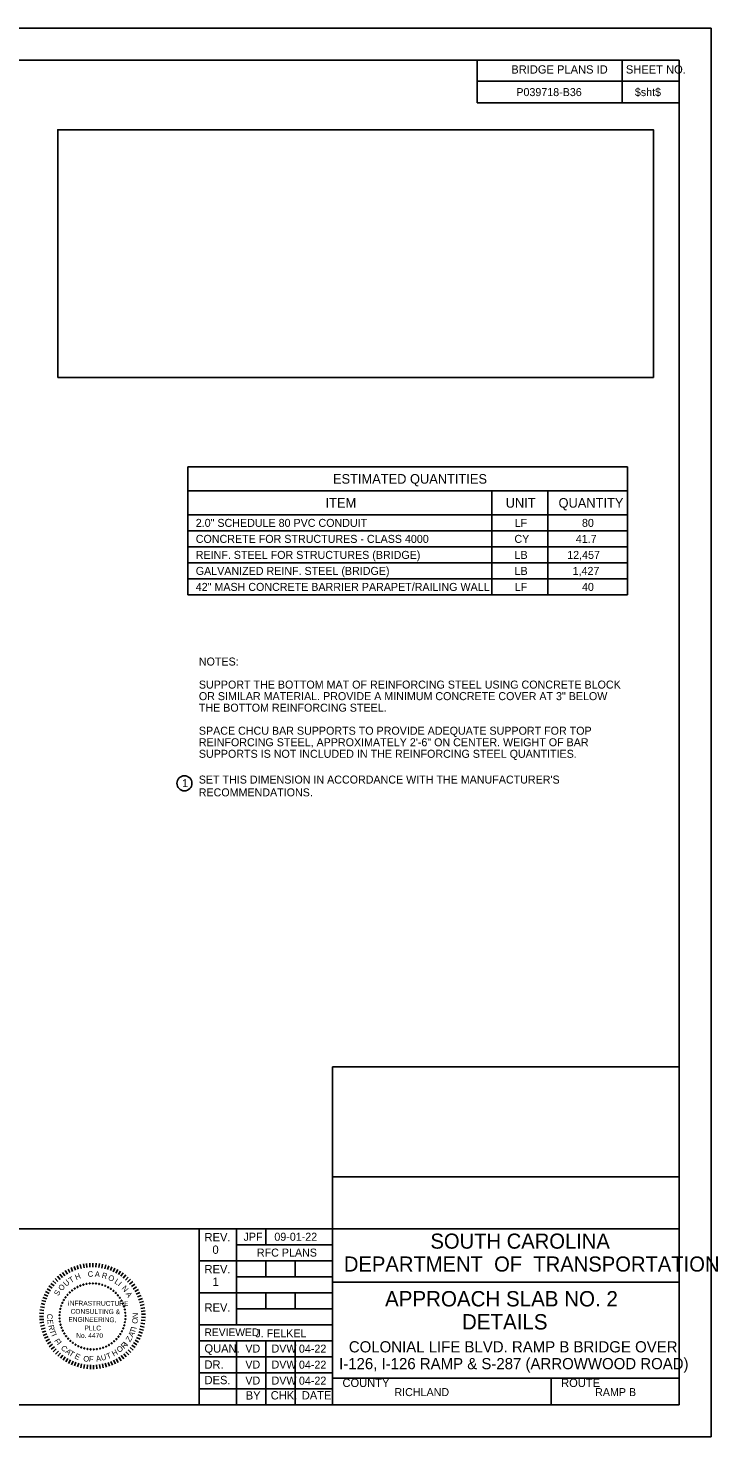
# Model space of a CAD drawing. Extents: x 2799.7 to 2896, y 515.2 to 573.9.
# Drawn here: x 2867.2 to 2896, y 515.2 to 573.9 of the extents above; entities that cross this region are included whole.
import ezdxf

# ---------------------------------------------------------------- set-up
doc = ezdxf.new("R2010")
doc.units = 0
for name, color, linetype in [('BR_AUTO DIMENSION', 7, 'Continuous'), ('BR_BORDER LINES', 7, 'Continuous'), ('BR_TABLE LINES', 7, 'Continuous'), ('BR_TEXT', 7, 'Continuous'), ('Level 31', 7, 'Continuous')]:
    doc.layers.add(name, color=color, linetype=linetype)

msp = doc.modelspace()

# ---------------------------------------------------------------- linework, layer by layer
at = {"layer": 'BR_AUTO DIMENSION'}
msp.add_lwpolyline([(2868.463, 559.346), (2893.292, 559.346), (2893.292, 569.657), (2868.463, 569.657)], close=True, dxfattribs=at)
msp.add_circle((2873.747, 542.44), 0.314, dxfattribs=at)
at = {"layer": 'BR_BORDER LINES'}
for p, q in [((2894.359, 572.556), (2804.582, 572.556)), ((2885.953, 570.779), (2885.953, 572.556)), ((2891.996, 570.779), (2891.996, 572.556)), ((2894.359, 516.556), (2894.359, 572.556)), ((2885.953, 571.678), (2894.359, 571.678)), ((2891.996, 571.678), (2894.359, 571.678)), ((2894.359, 570.779), (2885.953, 570.779)), ((2879.914, 516.556), (2879.914, 530.627)), ((2879.914, 530.627), (2894.359, 530.627)), ((2879.914, 526.054), (2894.359, 526.054)), ((2860.05, 523.89), (2874.358, 523.89)), ((2874.358, 516.556), (2874.358, 523.89)), ((2874.358, 523.89), (2894.359, 523.89)), ((2875.913, 523.89), (2875.913, 519.889)), ((2877.136, 523.223), (2877.136, 523.89)), ((2875.913, 523.223), (2879.914, 523.223)), ((2874.358, 522.556), (2879.914, 522.556)), ((2877.136, 521.889), (2877.136, 522.556)), ((2878.358, 521.889), (2878.358, 522.556)), ((2875.913, 521.889), (2879.914, 521.889)), ((2879.914, 521.667), (2879.914, 521.667)), ((2879.914, 521.667), (2894.359, 521.667)), ((2874.358, 521.223), (2879.914, 521.223)), ((2877.136, 520.556), (2877.136, 521.223)), ((2878.358, 520.556), (2878.358, 521.223)), ((2875.913, 520.556), (2879.914, 520.556)), ((2874.358, 519.889), (2879.914, 519.889)), ((2874.358, 519.223), (2879.914, 519.223)), ((2875.913, 519.223), (2875.913, 516.556)), ((2877.136, 519.223), (2877.136, 516.556)), ((2878.358, 519.223), (2878.358, 516.556)), ((2874.358, 518.556), (2879.914, 518.556)), ((2874.358, 517.889), (2879.914, 517.889)), ((2879.914, 517.667), (2894.359, 517.667)), ((2880.174, 517.667), (2894.359, 517.667)), ((2889.025, 516.556), (2889.025, 517.667)), ((2874.358, 517.223), (2879.914, 517.223)), ((2804.582, 516.556), (2894.359, 516.556))]:
    msp.add_line(p, q, dxfattribs=at)
at = {"layer": 'BR_TABLE LINES'}
for p, q in [((2873.885, 550.286), (2873.885, 555.619)), ((2873.89, 555.619), (2892.219, 555.619)), ((2892.219, 550.286), (2892.219, 555.619)), ((2873.89, 554.619), (2892.219, 554.619)), ((2886.552, 550.286), (2886.552, 554.619)), ((2888.886, 550.286), (2888.886, 554.619)), ((2873.89, 553.619), (2892.219, 553.619)), ((2873.89, 552.952), (2892.219, 552.952)), ((2873.89, 552.286), (2892.219, 552.286)), ((2873.89, 551.619), (2892.219, 551.619)), ((2873.89, 550.953), (2892.219, 550.953)), ((2873.885, 550.286), (2892.219, 550.286))]:
    msp.add_line(p, q, dxfattribs=at)
at = {"layer": 'BR_TEXT'}
for p, q in [((2868.78, 522.145), (2868.867, 521.999)), ((2868.898, 522.211), (2868.976, 522.06)), ((2869.019, 522.269), (2869.088, 522.114)), ((2869.144, 522.32), (2869.203, 522.161)), ((2869.271, 522.363), (2869.321, 522.2)), ((2869.401, 522.398), (2869.441, 522.233)), ((2869.533, 522.425), (2869.562, 522.258)), ((2869.666, 522.445), (2869.685, 522.276)), ((2869.8, 522.456), (2869.809, 522.286)), ((2869.935, 522.458), (2869.934, 522.289)), ((2870.069, 522.453), (2870.058, 522.284)), ((2870.203, 522.439), (2870.181, 522.271)), ((2870.336, 522.418), (2870.304, 522.251)), ((2870.468, 522.388), (2870.425, 522.224)), ((2870.597, 522.35), (2870.544, 522.189)), ((2870.723, 522.305), (2870.661, 522.147)), ((2870.847, 522.252), (2870.776, 522.098)), ((2870.967, 522.191), (2870.886, 522.042)), ((2868.177, 521.614), (2868.311, 521.509)), ((2868.264, 521.717), (2868.391, 521.604)), ((2868.356, 521.815), (2868.476, 521.695)), ((2868.454, 521.907), (2868.567, 521.78)), ((2868.558, 521.993), (2868.662, 521.859)), ((2868.667, 522.072), (2868.763, 521.932)), ((2871.084, 522.123), (2870.994, 521.979)), ((2871.196, 522.048), (2871.097, 521.91)), ((2871.303, 521.967), (2871.196, 521.835)), ((2871.405, 521.879), (2871.29, 521.754)), ((2871.501, 521.785), (2871.379, 521.667)), ((2871.592, 521.685), (2871.463, 521.575)), ((2871.676, 521.58), (2871.541, 521.478)), ((2867.848, 521.029), (2868.007, 520.97)), ((2867.9, 521.154), (2868.055, 521.085)), ((2867.958, 521.275), (2868.109, 521.196)), ((2868.025, 521.392), (2868.17, 521.305)), ((2868.098, 521.505), (2868.237, 521.409)), ((2871.754, 521.471), (2871.612, 521.377)), ((2871.825, 521.356), (2871.678, 521.271)), ((2871.889, 521.238), (2871.737, 521.162)), ((2871.945, 521.115), (2871.789, 521.049)), ((2871.994, 520.99), (2871.834, 520.933)), ((2867.722, 520.507), (2867.89, 520.488)), ((2867.741, 520.64), (2867.908, 520.611)), ((2867.769, 520.772), (2867.934, 520.732)), ((2867.805, 520.902), (2867.967, 520.852)), ((2872.035, 520.862), (2871.872, 520.815)), ((2872.068, 520.731), (2871.903, 520.694)), ((2872.094, 520.599), (2871.926, 520.572)), ((2872.111, 520.466), (2871.942, 520.449)), ((2867.707, 520.238), (2867.877, 520.24)), ((2867.71, 520.373), (2867.88, 520.364)), ((2867.712, 520.104), (2867.881, 520.115)), ((2867.725, 519.97), (2867.893, 519.992)), ((2867.746, 519.837), (2867.913, 519.869)), ((2872.074, 519.796), (2871.908, 519.831)), ((2872.098, 519.929), (2871.93, 519.953)), ((2872.113, 520.062), (2871.944, 520.077)), ((2872.12, 520.331), (2871.95, 520.325)), ((2872.121, 520.197), (2871.951, 520.201)), ((2867.775, 519.706), (2867.94, 519.748)), ((2867.812, 519.576), (2867.974, 519.628)), ((2867.858, 519.449), (2868.016, 519.511)), ((2867.91, 519.326), (2868.064, 519.397)), ((2867.97, 519.205), (2868.12, 519.286)), ((2871.837, 519.168), (2871.689, 519.252)), ((2871.9, 519.288), (2871.747, 519.362)), ((2871.955, 519.411), (2871.798, 519.475)), ((2872.002, 519.537), (2871.842, 519.591)), ((2872.042, 519.665), (2871.878, 519.71)), ((2868.038, 519.089), (2868.182, 519.178)), ((2868.112, 518.976), (2868.251, 519.075)), ((2868.193, 518.869), (2868.325, 518.975)), ((2868.281, 518.767), (2868.406, 518.881)), ((2868.374, 518.67), (2868.493, 518.792)), ((2868.474, 518.579), (2868.584, 518.708)), ((2868.578, 518.494), (2868.681, 518.629)), ((2871.322, 518.552), (2871.214, 518.682)), ((2871.423, 518.641), (2871.307, 518.765)), ((2871.519, 518.736), (2871.395, 518.852)), ((2871.608, 518.836), (2871.478, 518.945)), ((2871.691, 518.942), (2871.554, 519.043)), ((2871.768, 519.053), (2871.625, 519.145)), ((2868.688, 518.416), (2868.782, 518.557)), ((2868.802, 518.345), (2868.887, 518.491)), ((2868.92, 518.28), (2868.997, 518.432)), ((2869.042, 518.223), (2869.109, 518.379)), ((2869.168, 518.174), (2869.225, 518.334)), ((2869.296, 518.132), (2869.343, 518.295)), ((2869.426, 518.099), (2869.463, 518.264)), ((2869.558, 518.073), (2869.585, 518.24)), ((2869.691, 518.055), (2869.708, 518.224)), ((2869.826, 518.046), (2869.832, 518.215)), ((2869.96, 518.044), (2869.957, 518.214)), ((2870.095, 518.051), (2870.081, 518.221)), ((2870.229, 518.067), (2870.204, 518.235)), ((2870.361, 518.09), (2870.327, 518.256)), ((2870.492, 518.121), (2870.447, 518.285)), ((2870.621, 518.16), (2870.566, 518.321)), ((2870.747, 518.207), (2870.683, 518.364)), ((2870.87, 518.262), (2870.796, 518.415)), ((2870.99, 518.324), (2870.907, 518.472)), ((2871.105, 518.393), (2871.013, 518.536)), ((2871.216, 518.469), (2871.116, 518.606))]:
    msp.add_line(p, q, dxfattribs=at)
for centre, start, end in [((2869.535, 521.562), 16.14222, 196.14222), ((2869.535, 521.562), 196.14222, 16.14222), ((2869.664, 521.592), 10.60376, 190.60376), ((2869.664, 521.592), 190.60376, 10.60376), ((2869.796, 521.61), 5.06529, 185.06529), ((2869.796, 521.61), 185.06529, 5.06529), ((2869.928, 521.615), 359.52683, 179.52683), ((2869.928, 521.615), 179.52683, 359.52683), ((2870.061, 521.608), 353.98837, 173.98837), ((2870.061, 521.608), 173.98837, 353.98837), ((2870.192, 521.587), 348.44991, 168.44991), ((2870.192, 521.587), 168.44991, 348.44991), ((2870.321, 521.554), 162.91145, 342.91145), ((2870.321, 521.554), 342.91145, 162.91145), ((2868.791, 521.033), 54.91145, 234.91145), ((2868.791, 521.033), 234.91145, 54.91145), ((2868.872, 521.138), 49.37299, 229.37299), ((2868.872, 521.138), 229.37299, 49.37299), ((2868.964, 521.234), 43.83453, 223.83453), ((2868.964, 521.234), 223.83453, 43.83453), ((2869.064, 521.321), 38.29606, 218.29606), ((2869.064, 521.321), 218.29606, 38.29606), ((2869.173, 521.398), 32.7576, 212.7576), ((2869.173, 521.398), 212.7576, 32.7576), ((2869.288, 521.464), 27.21914, 207.21914), ((2869.288, 521.464), 207.21914, 27.21914), ((2869.409, 521.519), 21.68068, 201.68068), ((2869.409, 521.519), 201.68068, 21.68068), ((2870.446, 521.508), 157.37299, 337.37299), ((2870.446, 521.508), 337.37299, 157.37299), ((2870.566, 521.451), 151.83453, 331.83453), ((2870.566, 521.451), 331.83453, 151.83453), ((2870.68, 521.383), 146.29606, 326.29606), ((2870.68, 521.383), 326.29606, 146.29606), ((2870.786, 521.303), 140.7576, 320.7576), ((2870.786, 521.303), 320.7576, 140.7576), ((2870.885, 521.214), 135.21914, 315.21914), ((2870.885, 521.214), 315.21914, 135.21914), ((2870.974, 521.116), 129.68068, 309.68068), ((2870.974, 521.116), 309.68068, 129.68068), ((2871.054, 521.01), 124.14222, 304.14222), ((2871.054, 521.01), 304.14222, 124.14222), ((2868.551, 520.42), 82.60376, 262.60376), ((2868.551, 520.42), 262.60376, 82.60376), ((2868.575, 520.551), 77.06529, 257.06529), ((2868.575, 520.551), 257.06529, 77.06529), ((2868.611, 520.678), 71.52683, 251.52683), ((2868.611, 520.678), 251.52683, 71.52683), ((2868.659, 520.802), 65.98837, 245.98837), ((2868.659, 520.802), 245.98837, 65.98837), ((2868.719, 520.921), 60.44991, 240.44991), ((2868.719, 520.921), 240.44991, 60.44991), ((2871.123, 520.896), 118.60376, 298.60376), ((2871.123, 520.896), 298.60376, 118.60376), ((2871.181, 520.776), 113.06529, 293.06529), ((2871.181, 520.776), 293.06529, 113.06529), ((2871.227, 520.652), 107.52683, 287.52683), ((2871.227, 520.652), 287.52683, 107.52683), ((2871.26, 520.523), 101.98837, 281.98837), ((2871.26, 520.523), 281.98837, 101.98837), ((2871.281, 520.392), 96.44991, 276.44991), ((2871.281, 520.392), 276.44991, 96.44991), ((2868.54, 520.287), 88.14222, 268.14222), ((2868.542, 520.155), 93.68068, 273.68068), ((2868.556, 520.023), 99.21914, 279.21914), ((2868.54, 520.287), 268.14222, 88.14222), ((2868.542, 520.155), 273.68068, 93.68068), ((2868.556, 520.023), 279.21914, 99.21914), ((2868.584, 519.892), 104.7576, 284.7576), ((2868.584, 519.892), 284.7576, 104.7576), ((2871.237, 519.865), 74.29606, 254.29606), ((2871.237, 519.865), 254.29606, 74.29606), ((2871.267, 519.995), 79.83453, 259.83453), ((2871.267, 519.995), 259.83453, 79.83453), ((2871.285, 520.126), 85.37299, 265.37299), ((2871.289, 520.259), 90.91145, 270.91145), ((2871.285, 520.126), 265.37299, 85.37299), ((2871.289, 520.259), 270.91145, 90.91145), ((2868.624, 519.766), 110.29606, 290.29606), ((2868.624, 519.766), 290.29606, 110.29606), ((2868.675, 519.643), 115.83453, 295.83453), ((2868.675, 519.643), 295.83453, 115.83453), ((2868.739, 519.527), 121.37299, 301.37299), ((2868.739, 519.527), 301.37299, 121.37299), ((2868.813, 519.416), 126.91145, 306.91145), ((2868.813, 519.416), 306.91145, 126.91145), ((2868.898, 519.314), 132.44991, 312.44991), ((2868.898, 519.314), 312.44991, 132.44991), ((2868.992, 519.22), 137.98837, 317.98837), ((2868.992, 519.22), 317.98837, 137.98837), ((2870.816, 519.201), 41.06529, 221.06529), ((2870.816, 519.201), 221.06529, 41.06529), ((2870.912, 519.293), 46.60376, 226.60376), ((2870.912, 519.293), 226.60376, 46.60376), ((2870.998, 519.394), 52.14222, 232.14222), ((2870.998, 519.394), 232.14222, 52.14222), ((2871.075, 519.503), 57.68068, 237.68068), ((2871.075, 519.503), 237.68068, 57.68068), ((2871.141, 519.618), 63.21914, 243.21914), ((2871.141, 519.618), 243.21914, 63.21914), ((2871.195, 519.739), 68.7576, 248.7576), ((2871.195, 519.739), 248.7576, 68.7576), ((2869.095, 519.136), 143.52683, 323.52683), ((2869.095, 519.136), 323.52683, 143.52683), ((2869.205, 519.062), 149.06529, 329.06529), ((2869.205, 519.062), 329.06529, 149.06529), ((2869.322, 518.999), 154.60376, 334.60376), ((2869.322, 518.999), 334.60376, 154.60376), ((2869.445, 518.948), 160.14222, 340.14222), ((2869.445, 518.948), 340.14222, 160.14222), ((2869.572, 518.908), 345.68068, 165.68068), ((2869.572, 518.908), 165.68068, 345.68068), ((2869.702, 518.881), 351.21914, 171.21914), ((2869.702, 518.881), 171.21914, 351.21914), ((2869.834, 518.867), 356.7576, 176.7576), ((2869.834, 518.867), 176.7576, 356.7576), ((2869.967, 518.866), 2.29606, 182.29606), ((2869.967, 518.866), 182.29606, 2.29606), ((2870.099, 518.877), 7.83453, 187.83453), ((2870.099, 518.877), 187.83453, 7.83453), ((2870.23, 518.902), 13.37299, 193.37299), ((2870.23, 518.902), 193.37299, 13.37299), ((2870.357, 518.938), 18.91145, 198.91145), ((2870.357, 518.938), 198.91145, 18.91145), ((2870.481, 518.987), 24.44991, 204.44991), ((2870.481, 518.987), 204.44991, 24.44991), ((2870.599, 519.048), 29.98837, 209.98837), ((2870.599, 519.048), 209.98837, 29.98837), ((2870.711, 519.119), 35.52683, 215.52683), ((2870.711, 519.119), 215.52683, 35.52683)]:
    msp.add_arc(centre, 0.0187, start, end, dxfattribs=at)
at = {"layer": 'Level 31'}
msp.add_line((2887.137, 520.493), (2887.137, 520.493), dxfattribs=at)
msp.add_lwpolyline([(2799.693, 515.223), (2895.694, 515.223), (2895.694, 573.89), (2799.693, 573.89)], close=True, dxfattribs=at)

# ---------------------------------------------------------------- texts
at = {"layer": 'BR_TEXT'}
for s, height, p in [('BRIDGE PLANS ID', 0.34667, (2887.369, 571.998)), ('SHEET NO.', 0.3467, (2892.145, 571.998)), ('P039718-B36', 0.33334, (2887.579, 571.061)), ('$sht$', 0.3333, (2892.519, 571.061)), ('ESTIMATED QUANTITIES', 0.40001, (2879.937, 554.919)), ('ITEM', 0.4, (2879.63, 553.919)), ('UNIT', 0.4, (2887.136, 553.919)), ('QUANTITY', 0.4, (2889.338, 553.919)), ('2.0" SCHEDULE 80 PVC CONDUIT', 0.33334, (2874.219, 553.119)), ('LF', 0.3333, (2887.509, 553.119)), ('80', 0.3333, (2890.315, 553.119)), ('CONCRETE FOR STRUCTURES - CLASS 4000', 0.33334, (2874.219, 552.453)), ('CY', 0.3333, (2887.5, 552.453)), ('41.7', 0.3333, (2890.058, 552.453)), ('REINF. STEEL FOR STRUCTURES (BRIDGE)', 0.33334, (2874.219, 551.786)), ('LB', 0.3333, (2887.505, 551.786)), ('12,457', 0.3333, (2889.701, 551.786)), ('GALVANIZED REINF. STEEL (BRIDGE)', 0.33334, (2874.219, 551.119)), ('LB', 0.3333, (2887.507, 551.119)), ('1,427', 0.3333, (2889.925, 551.119)), ('42" MASH CONCRETE BARRIER PARAPET/RAILING WALL', 0.33334, (2874.219, 550.453)), ('LF', 0.3333, (2887.513, 550.453)), ('40', 0.3333, (2890.315, 550.453)), ("SET THIS DIMENSION IN ACCORDANCE WITH THE MANUFACTURER'S", 0.33332, (2874.343, 542.429)), ('RECOMMENDATIONS.', 0.33332, (2874.343, 541.896)), ('REV.', 0.3467, (2874.584, 523.364)), ('JPF', 0.3333, (2876.211, 523.389)), ('09-01-22', 0.3333, (2877.494, 523.389)), ('SOUTH CAROLINA', 0.629, (2883.999, 523.059)), ('0', 0.347, (2874.914, 522.844)), ('RFC PLANS', 0.3333, (2876.767, 522.729)), ('DEPARTMENT  OF  TRANSPORTATION', 0.629, (2880.392, 522.105)), ('REV.', 0.3467, (2874.584, 522.031)), ('1', 0.347, (2874.919, 521.511)), ('APPROACH SLAB NO. 2', 0.64001, (2882.107, 520.653)), ('REV.', 0.3467, (2874.584, 520.437)), ('DETAILS', 0.64, (2885.312, 519.693)), ('REVIEWED', 0.32, (2874.582, 519.419)), ('J. FELKEL', 0.3333, (2876.702, 519.368)), ('COLONIAL LIFE BLVD. RAMP B BRIDGE OVER', 0.46667, (2880.598, 518.738)), ('QUAN.', 0.3467, (2874.58, 518.73)), ('VD', 0.3333, (2876.285, 518.733)), ('DVW', 0.3333, (2877.377, 518.733)), ('04-22', 0.3333, (2878.519, 518.727)), ('DR.', 0.3467, (2874.581, 518.059)), ('VD', 0.3333, (2876.285, 518.067)), ('DVW', 0.3333, (2877.377, 518.067)), ('04-22', 0.3333, (2878.519, 518.06)), ('I-126, I-126 RAMP & S-287 (ARROWWOOD ROAD) ', 0.46667, (2880.192, 518.038)), ('DES.', 0.3467, (2874.584, 517.415)), ('VD', 0.3333, (2876.285, 517.4)), ('DVW', 0.3333, (2877.377, 517.4)), ('04-22', 0.3333, (2878.519, 517.394)), ('COUNTY', 0.3467, (2880.333, 517.298)), ('ROUTE', 0.3467, (2889.445, 517.298)), ('BY', 0.3467, (2876.301, 516.774)), ('CHK.', 0.3467, (2877.343, 516.778)), ('DATE', 0.3467, (2878.637, 516.778)), ('RICHLAND', 0.3333, (2882.499, 516.919)), ('RAMP B', 0.3333, (2890.862, 516.919))]:
    msp.add_text(s, height=height, dxfattribs=at).set_placement(p)
for s, height, rotation, p in [('NOTES:', 0.3333, 360, (2874.348, 547.345)), ('SUPPORT THE BOTTOM MAT OF REINFORCING STEEL USING CONCRETE BLOCK ', 0.33333, 360, (2874.348, 546.385)), ('OR SIMILAR MATERIAL. PROVIDE A MINIMUM CONCRETE COVER AT 3" BELOW ', 0.33333, 360, (2874.348, 545.904)), ('THE BOTTOM REINFORCING STEEL. ', 0.33333, 360, (2874.348, 545.424)), ('SPACE CHCU BAR SUPPORTS TO PROVIDE ADEQUATE SUPPORT FOR TOP ', 0.33333, 360, (2874.348, 544.464)), ('REINFORCING STEEL, APPROXIMATELY 2\'-6" ON CENTER. WEIGHT OF BAR ', 0.33333, 360, (2874.348, 543.983)), ('SUPPORTS IS NOT INCLUDED IN THE REINFORCING STEEL QUANTITIES. ', 0.33333, 360, (2874.348, 543.503)), ('1', 0.333, 360, (2873.65, 542.28)), ('O', 0.233, 49.87824, (2868.639, 521.28)), ('U', 0.233, 40.84822, (2868.818, 521.47)), ('T', 0.233, 31.81819, (2869.013, 521.619)), ('H', 0.233, 22.78817, (2869.24, 521.746)), ('C', 0.233, 4.72812, (2869.727, 521.878)), ('A', 0.233, 355.69809, (2870.006, 521.891)), ('R', 0.233, 346.66807, (2870.284, 521.846)), ('O', 0.233, 337.63804, (2870.544, 521.767)), ('L', 0.233, 327.10802, (2870.808, 521.632)), ('I', 0.233, 319.578, (2870.948, 521.531)), ('S', 0.233, 58.90827, (2868.491, 521.072)), ('N', 0.233, 310.54797, (2871.11, 521.396)), ('A', 0.233, 301.51795, (2871.284, 521.176)), ('INFRASTRUCTURE', 0.19939, 359.52683, (2868.888, 520.692)), ('CONSULTING &', 0.19939, 359.52683, (2868.998, 520.349)), ('C', 0.233, 267.02504, (2868.025, 520.352)), ('E', 0.233, 273.02504, (2868.036, 520.108)), ('R', 0.233, 279.02504, (2868.07, 519.862)), ('ENGINEERING,', 0.19939, 359.52683, (2868.908, 520.014)), ('PLLC', 0.1994, 359.52683, (2869.579, 519.658)), ('I', 0.233, 77.90926, (2871.744, 519.697)), ('O', 0.233, 83.20849, (2871.786, 519.922)), ('N', 0.233, 89.20849, (2871.815, 520.166)), ('T', 0.233, 285.02504, (2868.117, 519.652)), ('I', 0.233, 293.77127, (2868.196, 519.457)), ('F', 0.233, 299.77127, (2868.306, 519.227)), ('No. 4470', 0.1994, 359.52683, (2869.234, 519.346)), ('Z', 0.233, 57.39539, (2871.477, 519.153)), ('A', 0.233, 63.39539, (2871.594, 519.356)), ('T', 0.233, 69.39539, (2871.676, 519.517)), ('I', 0.233, 308.52683, (2868.418, 519.084)), ('C', 0.233, 314.52683, (2868.577, 518.897)), ('A', 0.233, 320.52683, (2868.761, 518.74)), ('T', 0.233, 326.52683, (2868.906, 518.638)), ('E', 0.233, 332.52683, (2869.142, 518.51)), ('U', 0.233, 16.52683, (2870.303, 518.387)), ('T', 0.233, 22.52683, (2870.548, 518.452)), ('H', 0.233, 28.52683, (2870.796, 518.564)), ('O', 0.233, 38.52683, (2871.031, 518.713)), ('R', 0.233, 44.52683, (2871.236, 518.873)), ('I', 0.233, 52.33388, (2871.367, 518.999)), ('O', 0.233, 350.52683, (2869.516, 518.38)), ('F', 0.233, 356.52683, (2869.76, 518.356)), ('A', 0.233, 10.52683, (2870.08, 518.351))]:
    msp.add_text(s, height=height, rotation=rotation, dxfattribs=at).set_placement(p)

doc.saveas('drawing.dxf')
